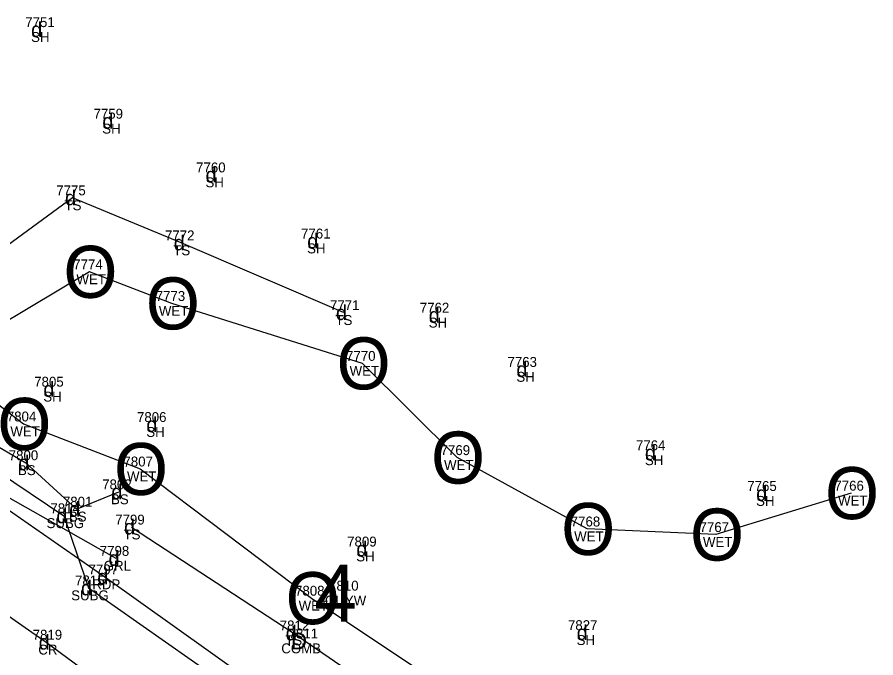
# Model space of a CAD drawing. Extents: x 69415 to 80913, y 7576 to 15059.
# Drawn here: x 76564.6 to 76737.9, y 13935.5 to 14064.7 of the extents above; entities that cross this region are included whole.
import ezdxf

# ---------------------------------------------------------------- set-up
doc = ezdxf.new("R2010")
doc.units = 0
for name, color, linetype in [('Level 11', 7, 'Continuous'), ('Level 12', 7, 'Continuous'), ('Level 15', 7, 'Continuous'), ('Level 16', 7, 'Continuous'), ('Level 46', 7, 'Continuous'), ('Level 47', 7, 'Continuous'), ('Level 48', 7, 'Continuous')]:
    doc.layers.add(name, color=color, linetype=linetype)

msp = doc.modelspace()

# ---------------------------------------------------------------- linework, layer by layer
at = {"layer": 'Level 11'}
for p, q in [((76555.91, 13970.17), (76582.3, 13951.78)), ((76582.3, 13951.78), (76612.2, 13930.52))]:
    msp.add_line(p, q, dxfattribs=at)
at = {"layer": 'Level 12'}
msp.add_line((76556.53, 13971.43), (76584.56, 13955.53), dxfattribs=at)
at = {"layer": 'Level 15'}
for p, q in [((76509.89, 14007.1), (76574.03, 13964.12)), ((76574.03, 13964.12), (76579.01, 13949.56)), ((76579.01, 13949.56), (76648.98, 13900.68))]:
    msp.add_line(p, q, dxfattribs=at)
at = {"layer": 'Level 16'}
for p, q in [((76579.21, 14013.32), (76557.99, 14000.62)), ((76595.85, 14006.95), (76579.21, 14013.32)), ((76634.34, 13994.85), (76595.85, 14006.95)), ((76549.13, 13995.62), (76565.88, 13982.64)), ((76653.39, 13975.85), (76634.34, 13994.85)), ((76565.88, 13982.64), (76589.42, 13973.55)), ((76679.65, 13961.45), (76653.39, 13975.85)), ((76589.42, 13973.55), (76624.05, 13947.49)), ((76732.9, 13968.68), (76705.65, 13960.32)), ((76705.65, 13960.32), (76679.65, 13961.45)), ((76624.05, 13947.49), (76662.08, 13922.17))]:
    msp.add_line(p, q, dxfattribs=at)
at = {"layer": 'Level 48'}
for p, q in [((76575.78, 14028.25), (76554.11, 14012.41)), ((76597.72, 14019.16), (76575.78, 14028.25)), ((76630.45, 14005.09), (76597.72, 14019.16)), ((76537.44, 13991.63), (76566.36, 13974.81)), ((76566.36, 13974.81), (76576.63, 13965.45)), ((76576.63, 13965.45), (76585.13, 13968.94)), ((76531.82, 13965.66), (76570.47, 13938.61)), ((76587.69, 13961.84), (76620.31, 13940.48)), ((76620.31, 13940.48), (76657.22, 13915.3)), ((76570.47, 13938.61), (76604.32, 13913.85))]:
    msp.add_line(p, q, dxfattribs=at)

# ---------------------------------------------------------------- texts
at = {"layer": 'Level 15'}
for s, height, p in [('4', 11.5, (76624.61, 13942.76)), ('D', 3.4, (76619.84, 13937.16))]:
    msp.add_text(s, height=height, dxfattribs=at).set_placement(p)
at = {"layer": 'Level 16'}
for p in [(76573.96, 14008.07), (76590.6, 14001.7), (76629.09, 13989.6), (76560.63, 13977.39), (76648.14, 13970.6), (76584.17, 13968.3), (76727.65, 13963.43), (76674.4, 13956.2), (76700.4, 13955.07), (76618.8, 13942.24)]:
    msp.add_text('O', height=10.5, dxfattribs=at).set_placement(p)
at = {"layer": 'Level 46'}
for s, p in [('7751', (76566.26, 14062.69)), ('SH', (76567.44, 14059.69)), ('7759', (76580.04, 14044.21)), ('SH', (76581.8, 14041.21)), ('7760', (76600.74, 14033.38)), ('SH', (76602.63, 14030.38)), ('7775', (76572.52, 14028.75)), ('TS', (76574.19, 14025.75)), ('7772', (76594.46, 14019.66)), ('7761', (76621.92, 14020.04)), ('TS', (76596.13, 14016.66)), ('SH', (76623.15, 14017.04)), ('7774', (76575.95, 14013.82)), ('WET', (76576.59, 14010.82)), ('7773', (76592.59, 14007.45)), ('7771', (76627.76, 14005.59)), ('WET', (76593.23, 14004.45)), ('7762', (76645.88, 14005.08)), ('TS', (76628.86, 14002.59)), ('SH', (76647.68, 14002.08)), ('7770', (76631, 13995.35)), ('7763', (76663.57, 13994.14)), ('WET', (76631.72, 13992.35)), ('7805', (76568.07, 13990.15)), ('SH', (76665.37, 13991.14)), ('SH', (76569.9, 13987.15)), ('7804', (76562.54, 13983.14)), ('7806', (76588.81, 13983.02)), ('WET', (76563.26, 13980.14)), ('SH', (76590.69, 13980.02)), ('7769', (76650.08, 13976.35)), ('7764', (76689.5, 13977.32)), ('7800', (76562.93, 13975.31)), ('7807', (76586.08, 13974.05)), ('SH', (76691.3, 13974.32)), ('BS', (76564.8, 13972.31)), ('WET', (76650.77, 13973.35)), ('WET', (76586.8, 13971.05)), ('7802', (76581.79, 13969.44)), ('7765', (76711.96, 13969.11)), ('7766', (76729.54, 13969.18)), ('7801', (76573.86, 13965.95)), ('BS', (76583.57, 13966.44)), ('SH', (76713.75, 13966.11)), ('WET', (76730.28, 13966.18)), ('7814', (76571.34, 13964.62)), ('BS', (76575.07, 13962.95)), ('7799', (76584.42, 13962.34)), ('7768', (76676.34, 13961.95)), ('SUBG', (76570.56, 13961.62)), ('7767', (76702.34, 13960.82)), ('TS', (76586.1, 13959.34)), ('WET', (76677.03, 13958.95)), ('7809', (76631.22, 13957.91)), ('WET', (76703.02, 13957.82)), ('7798', (76581.3, 13956.03)), ('SH', (76633.05, 13954.91)), ('7797', (76579.04, 13952.28)), ('GRL', (76582.1, 13953.03)), ('7815', (76576.32, 13950.06)), ('RDP', (76579.79, 13949.28)), ('7808', (76620.71, 13947.99)), ('7810', (76627.58, 13949.01)), ('SUBG', (76575.54, 13947.06)), ('WET', (76621.43, 13944.99)), ('GUYW', (76626.75, 13946.01)), ('7827', (76675.78, 13941.04)), ('7812', (76617.62, 13940.98)), ('7811', (76619.41, 13939.36)), ('7819', (76567.76, 13939.11)), ('TS', (76618.72, 13937.98)), ('SH', (76677.53, 13938.04)), ('CR', (76568.9, 13936.11)), ('COMB', (76617.93, 13936.36))]:
    msp.add_text(s, height=2, dxfattribs=at).set_placement(p)
at = {"layer": 'Level 47'}
for p in [(76567.45, 14060.69), (76581.81, 14042.21), (76602.64, 14031.38), (76574.28, 14026.75), (76623.16, 14018.04), (76596.22, 14017.66), (76628.95, 14003.59), (76647.69, 14003.08), (76665.38, 13992.14), (76569.91, 13988.15), (76590.7, 13981.02), (76691.31, 13975.32), (76564.86, 13973.31), (76583.63, 13967.44), (76713.76, 13967.11), (76572.53, 13962.62), (76575.13, 13963.95), (76586.19, 13960.34), (76633.07, 13955.91), (76583.06, 13954.03), (76580.8, 13950.28), (76577.51, 13948.06), (76618.81, 13938.98), (76677.54, 13939.04), (76568.97, 13937.11)]:
    msp.add_text('d', height=3, dxfattribs=at).set_placement(p)

doc.saveas('drawing.dxf')
